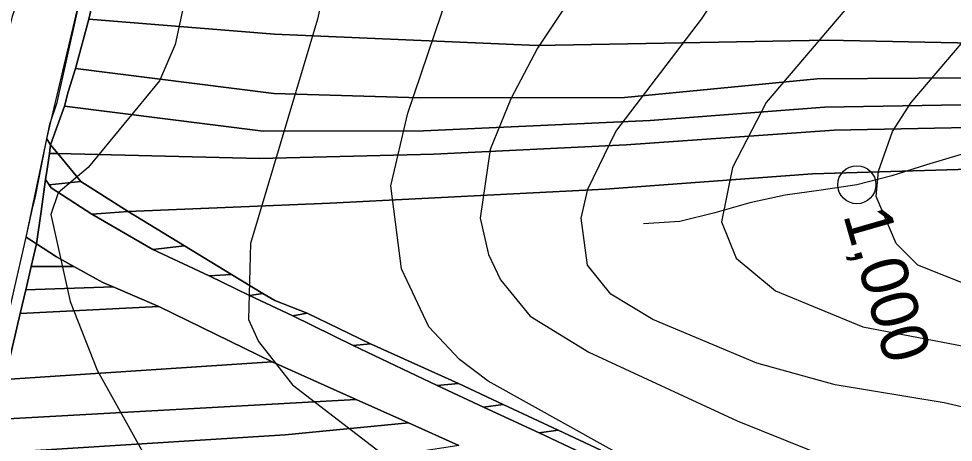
# Model space of a CAD drawing. Extents: x -510989 to -501240, y -1184665 to -1176098.
# Drawn here: x -510512.6 to -510254.5, y -1180348.9 to -1180231.9 of the extents above; entities that cross this region are included whole.
import ezdxf

# ---------------------------------------------------------------- set-up
doc = ezdxf.new("R2010")
doc.units = 0
for name, color, linetype in [('lesni_pozemek', 7, 'Continuous'), ('NAVRH_rozvodnice', 7, 'Continuous'), ('ostatni_plocha_x_ostatni_komunikace', 7, 'Continuous'), ('ostatni_plocha_x_silnice', 7, 'Continuous'), ('popis', 7, 'Continuous'), ('STAV_povodi', 7, 'Continuous'), ('trasovani_toku', 7, 'Continuous'), ('vrstevnice_01', 7, 'Continuous'), ('vrstevnice_02', 7, 'Continuous')]:
    doc.layers.add(name, color=color, linetype=linetype)

msp = doc.modelspace()

# ---------------------------------------------------------------- linework, layer by layer
at = {"layer": 'lesni_pozemek'}
for points in [[(-509976.21, -1180207.83), (-510053.14, -1180227.79), (-510097.37, -1180234.14), (-510131.29, -1180239.56), (-510208.41, -1180239.45), (-510289.34, -1180237.75), (-510369.43, -1180239.24), (-510441.97, -1180236.15), (-510493.25, -1180231.97), (-510490.8, -1180221.41), (-510439.3, -1180225.49), (-510373.63, -1180226.09), (-510299.64, -1180228.54), (-510217.22, -1180229.31), (-510131.92, -1180230.11), (-510096.09, -1180227.74), (-510054.98, -1180217.41), (-509976.43, -1180197.65)], [(-509978.83, -1180219.44), (-510095.15, -1180243.03), (-510141.46, -1180247.99), (-510208.48, -1180247.92), (-510292.16, -1180248.46), (-510345.34, -1180253.6), (-510401.71, -1180253.7), (-510442.19, -1180252.49), (-510496.95, -1180245.59), (-510493.25, -1180231.97), (-510441.97, -1180236.15), (-510369.43, -1180239.24), (-510289.34, -1180237.75), (-510208.41, -1180239.45), (-510131.29, -1180239.56), (-510097.37, -1180234.14), (-510053.14, -1180227.79), (-509976.21, -1180207.83)], [(-509982.33, -1180228.02), (-510010.82, -1180233.61), (-510050.96, -1180240.32), (-510082.98, -1180248.06), (-510141.78, -1180256.57), (-510209.33, -1180254.93), (-510290.12, -1180256.29), (-510338.24, -1180260), (-510400.79, -1180262.88), (-510445.12, -1180262.95), (-510499.99, -1180256), (-510498.92, -1180252.05), (-510496.95, -1180245.59), (-510442.19, -1180252.49), (-510401.71, -1180253.7), (-510345.34, -1180253.6), (-510292.16, -1180248.46), (-510208.48, -1180247.92), (-510141.46, -1180247.99), (-510095.15, -1180243.03), (-509978.83, -1180219.44)], [(-510011.1, -1180238), (-510020.32, -1180240.09), (-510080.31, -1180253.72), (-510141.54, -1180261.25), (-510222.72, -1180261.39), (-510287.42, -1180262.67), (-510344.9, -1180266.74), (-510397.95, -1180269.27), (-510446.13, -1180270.48), (-510501.79, -1180269.13), (-510503.79, -1180266.72), (-510499.99, -1180256), (-510445.12, -1180262.95), (-510400.79, -1180262.88), (-510338.24, -1180260), (-510290.12, -1180256.29), (-510209.33, -1180254.93), (-510141.78, -1180256.57), (-510082.98, -1180248.06), (-510050.96, -1180240.32), (-510010.82, -1180233.61)], [(-510019.77, -1180245.47), (-510025.75, -1180247), (-510024.37, -1180252.44), (-510049.58, -1180258.88), (-510074.58, -1180265.09), (-510127.81, -1180273.09), (-510135.55, -1180274.18), (-510175.03, -1180275.08), (-510222.23, -1180272.63), (-510293.37, -1180274.7), (-510350.62, -1180278.94), (-510426.62, -1180282.83), (-510482.39, -1180285.11), (-510495.43, -1180276.82), (-510501.79, -1180269.13), (-510446.13, -1180270.48), (-510397.95, -1180269.27), (-510344.9, -1180266.74), (-510287.42, -1180262.67), (-510222.72, -1180261.39), (-510141.54, -1180261.25), (-510080.31, -1180253.72), (-510020.32, -1180240.09)], [(-510502.15, -1180297.64), (-510497.34, -1180300.32), (-510509.16, -1180300.32), (-510507.71, -1180294.08)], [(-510509.16, -1180300.32), (-510497.34, -1180300.32), (-510489.41, -1180304.74), (-510486.54, -1180305.97), (-510510.66, -1180306.76)], [(-510510.66, -1180306.76), (-510486.54, -1180305.97), (-510473.89, -1180311.35), (-510512.19, -1180313.34)], [(-510473.89, -1180311.35), (-510442.62, -1180326.63), (-510516.44, -1180331.58), (-510512.19, -1180313.34)], [(-510516.44, -1180331.58), (-510442.62, -1180326.63), (-510419.42, -1180337.05), (-510518.99, -1180342.55)], [(-510518.99, -1180342.55), (-510419.42, -1180337.05), (-510404.98, -1180343.53), (-510439.03, -1180346.85), (-510521.19, -1180352)], [(-510404.98, -1180343.53), (-510391.06, -1180349.79), (-510423.89, -1180354.83), (-510523.59, -1180362.32), (-510521.19, -1180352), (-510439.03, -1180346.85)]]:
    msp.add_lwpolyline(points, close=True, dxfattribs=at)
msp.add_lwpolyline([(-510351.83, -1180351.05), (-510363.64, -1180345.53), (-510378.86, -1180338.45), (-510391.17, -1180332.69), (-510415.44, -1180321.67), (-510432.97, -1180313.17), (-510441.91, -1180309.76), (-510445.21, -1180307.75), (-510453.82, -1180302.51), (-510466.83, -1180294.58), (-510482.39, -1180285.11), (-510426.62, -1180282.83), (-510350.62, -1180278.94), (-510293.37, -1180274.7), (-510222.23, -1180272.63)], dxfattribs=at)
at = {"layer": 'NAVRH_rozvodnice'}
msp.add_arc((-510426.72, -1180257.64), 91.54, 153.6464, 172.807, dxfattribs=at)
at = {"layer": 'ostatni_plocha_x_ostatni_komunikace'}
for points in [[(-510513.58, -1180127.99), (-510512.03, -1180136.02), (-510510.77, -1180142.53), (-510509.13, -1180151.06), (-510507.55, -1180159.24), (-510505.88, -1180167.93), (-510502.92, -1180183.27), (-510494.49, -1180207.28), (-510492.02, -1180214.31), (-510490.29, -1180219.24), (-510490.8, -1180221.41), (-510493.25, -1180231.97), (-510496.95, -1180245.59), (-510498.92, -1180252.05), (-510499.99, -1180256), (-510503.79, -1180266.72), (-510504.8, -1180265.01), (-510504, -1180261), (-510502, -1180255), (-510494, -1180219), (-510506, -1180185), (-510544, -1179990)], [(-510530, -1180377), (-510510.58, -1180292.25), (-510507.71, -1180294.08), (-510509.16, -1180300.32), (-510510.66, -1180306.76), (-510512.19, -1180313.34), (-510516.44, -1180331.58), (-510518.99, -1180342.55), (-510521.19, -1180352)]]:
    msp.add_lwpolyline(points, dxfattribs=at)
at = {"layer": 'ostatni_plocha_x_silnice'}
for points in [[(-510503.79, -1180266.72), (-510504.13, -1180269.08), (-510504.76, -1180273.45), (-510505.17, -1180276.32), (-510506.43, -1180285.11), (-510507.71, -1180294.08), (-510510.58, -1180292.25), (-510508.57, -1180283.47), (-510508, -1180281), (-510506.21, -1180272.04), (-510504.8, -1180265.01)], [(-510503.79, -1180266.72), (-510501.79, -1180269.13), (-510504.13, -1180269.08)], [(-510501.79, -1180269.13), (-510495.43, -1180276.82), (-510500.7, -1180277.39), (-510504.18, -1180277.76), (-510505.17, -1180276.32), (-510504.76, -1180273.45), (-510504.13, -1180269.08)], [(-510495.43, -1180276.82), (-510482.39, -1180285.11), (-510489.8, -1180285.67), (-510492.4, -1180285.87), (-510503.63, -1180278.57), (-510504.18, -1180277.76), (-510500.7, -1180277.39)], [(-510489.8, -1180285.67), (-510482.39, -1180285.11), (-510466.83, -1180294.58), (-510475.6, -1180295.59), (-510492.4, -1180285.87)], [(-510475.6, -1180295.59), (-510466.83, -1180294.58), (-510453.82, -1180302.51), (-510460, -1180302.93)], [(-510460, -1180302.93), (-510453.82, -1180302.51), (-510445.21, -1180307.75), (-510448.85, -1180308.31)], [(-510448.85, -1180308.31), (-510445.21, -1180307.75), (-510441.91, -1180309.76), (-510432.97, -1180313.17), (-510436.91, -1180313.96)], [(-510436.91, -1180313.96), (-510432.97, -1180313.17), (-510415.44, -1180321.67), (-510420.29, -1180322.19)], [(-510420.29, -1180322.19), (-510415.44, -1180321.67), (-510391.17, -1180332.69), (-510397.07, -1180333.22)], [(-510391.17, -1180332.69), (-510378.86, -1180338.45), (-510384.24, -1180339.23), (-510397.07, -1180333.22)], [(-510378.86, -1180338.45), (-510363.64, -1180345.53), (-510368.89, -1180346.32), (-510384.24, -1180339.23)], [(-510368.89, -1180346.32), (-510363.64, -1180345.53), (-510351.83, -1180351.05), (-510357.21, -1180351.83)]]:
    msp.add_lwpolyline(points, close=True, dxfattribs=at)
msp.add_lwpolyline([(-510391.06, -1180349.79), (-510404.98, -1180343.53), (-510419.42, -1180337.05), (-510442.62, -1180326.63), (-510473.89, -1180311.35), (-510486.54, -1180305.97), (-510489.41, -1180304.74), (-510497.34, -1180300.32), (-510502.15, -1180297.64), (-510507.71, -1180294.08), (-510506.43, -1180285.11), (-510505.17, -1180276.32), (-510504.18, -1180277.76), (-510503.63, -1180278.57), (-510492.4, -1180285.87), (-510475.6, -1180295.59), (-510460, -1180302.93), (-510448.85, -1180308.31), (-510436.91, -1180313.96), (-510420.29, -1180322.19), (-510397.07, -1180333.22), (-510384.24, -1180339.23), (-510368.89, -1180346.32), (-510357.21, -1180351.83)], dxfattribs=at)
at = {"layer": 'popis'}
msp.add_lwpolyline([(-510622, -1180586), (-510612, -1180552), (-510587, -1180499), (-510562, -1180446), (-510530, -1180377), (-510520.29, -1180334.62), (-510510.58, -1180292.25), (-510504.8, -1180265.01), (-510494, -1180219), (-510506, -1180185), (-510525, -1180087.5), (-510544, -1179990)], dxfattribs=at)
at = {"layer": 'STAV_povodi'}
msp.add_arc((-510426.72, -1180257.64), 91.54, 153.6464, 172.807, dxfattribs=at)
at = {"layer": 'trasovani_toku'}
for p, q in [((-510252.35, -1180269.42), (-510261.93, -1180272.28)), ((-510261.93, -1180272.28), (-510271.49, -1180275.24)), ((-510271.49, -1180275.24), (-510281.17, -1180277.73)), ((-510281.17, -1180277.73), (-510291.05, -1180279.26)), ((-510300.96, -1180280.65), (-510310.74, -1180282.71)), ((-510291.05, -1180279.26), (-510300.96, -1180280.65)), ((-510310.74, -1180282.71), (-510320.34, -1180285.51)), ((-510320.34, -1180285.51), (-510330.06, -1180287.87)), ((-510330.06, -1180287.87), (-510340.04, -1180288.53))]:
    msp.add_line(p, q, dxfattribs=at)
msp.add_circle((-510281.17, -1180277.73), 5.25, dxfattribs=at)
at = {"layer": 'vrstevnice_01'}
for points in [[(-510226.91, -1180345), (-510257.09, -1180338), (-510287.19, -1180333), (-510308.81, -1180327), (-510337.5, -1180315), (-510349.09, -1180308), (-510355.5, -1180300), (-510357.31, -1180287), (-510355.41, -1180279), (-510347.69, -1180263), (-510324.09, -1180232), (-510305.59, -1180204), (-510290.5, -1180174), (-510281.91, -1180146), (-510278.81, -1180121), (-510280, -1180108), (-510283.91, -1180092), (-510296.81, -1180052), (-510300.19, -1180035), (-510301.41, -1180021), (-510297.19, -1179957)], [(-510429.81, -1179973), (-510434.41, -1180015), (-510434.41, -1180045), (-510430.31, -1180081), (-510431.41, -1180102), (-510460.41, -1180197), (-510469.41, -1180239), (-510473.69, -1180249), (-510493.41, -1180273)], [(-510339.81, -1180356), (-510383, -1180332), (-510390.91, -1180326), (-510399.31, -1180317), (-510406.91, -1180301), (-510409.81, -1180278), (-510405.19, -1180258), (-510394, -1180225), (-510375.31, -1180193), (-510360.81, -1180165), (-510352.91, -1180146), (-510349.41, -1180131), (-510348.41, -1180119), (-510351, -1180096), (-510367.19, -1180053), (-510368.31, -1180039), (-510367.91, -1180024), (-510360.41, -1179979)], [(-510012.5, -1180313), (-510054.5, -1180320), (-510112.5, -1180318), (-510149.31, -1180321), (-510182.41, -1180318), (-510240.81, -1180309), (-510249.09, -1180306), (-510264.31, -1180300), (-510270.31, -1180294), (-510275.81, -1180281), (-510275.19, -1180274), (-510271.31, -1180263), (-510266.19, -1180255), (-510223.69, -1180205), (-510206.69, -1180181), (-510197.41, -1180162), (-510191.19, -1180144), (-510188.91, -1180125), (-510191.69, -1180101), (-510196.81, -1180087), (-510225.69, -1180034), (-510235.09, -1180002)], [(-510493.41, -1180273), (-510501.69, -1180280), (-510503.69, -1180286), (-510498.41, -1180310), (-510490.91, -1180329), (-510467, -1180372), (-510464.19, -1180384), (-510465.41, -1180399), (-510467.81, -1180408), (-510475.69, -1180423), (-510496.41, -1180446), (-510520.31, -1180470), (-510530.91, -1180486), (-510538.31, -1180504), (-510543.91, -1180522), (-510547.31, -1180541), (-510549.5, -1180565), (-510550.19, -1180590)]]:
    msp.add_lwpolyline(points, dxfattribs=at)
at = {"layer": 'vrstevnice_02'}
for points in [[(-510326.41, -1179956), (-510339.5, -1180015), (-510339, -1180034), (-510336.69, -1180043), (-510318.5, -1180089), (-510314.81, -1180104), (-510313.19, -1180133), (-510322.09, -1180161), (-510339.31, -1180195), (-510369.31, -1180240), (-510376.69, -1180254), (-510382.41, -1180268), (-510385.19, -1180287), (-510382.91, -1180297), (-510379.59, -1180304), (-510371.41, -1180314), (-510355.19, -1180324), (-510314.19, -1180343), (-510266.91, -1180362), (-510251.09, -1180370)], [(-510264.91, -1180023), (-510235.19, -1180089), (-510228.81, -1180121), (-510228.81, -1180137), (-510231.5, -1180151), (-510240.59, -1180172), (-510269.69, -1180212), (-510306.19, -1180255), (-510315.5, -1180273), (-510318.5, -1180288), (-510314.5, -1180298), (-510303.59, -1180307), (-510279.5, -1180317), (-510154.09, -1180341), (-510109.69, -1180346), (-510082.09, -1180352), (-510067, -1180357), (-509991.69, -1180387)], [(-510401.41, -1180143), (-510421, -1180191), (-510430.09, -1180232), (-510448.59, -1180294), (-510449.19, -1180315), (-510446.41, -1180321), (-510437, -1180333), (-510375.91, -1180380), (-510370.31, -1180390), (-510367.81, -1180400), (-510368.5, -1180409), (-510373.19, -1180418), (-510424.41, -1180461), (-510438.81, -1180472), (-510478.31, -1180492), (-510500.31, -1180511), (-510506.81, -1180521), (-510512.81, -1180535), (-510516.19, -1180554), (-510514.31, -1180579), (-510517.91, -1180603)]]:
    msp.add_lwpolyline(points, dxfattribs=at)

# ---------------------------------------------------------------- texts
at = {"layer": 'trasovani_toku'}
msp.add_text('1,000', height=13, rotation=286.0844, dxfattribs=at).set_placement((-510285.01, -1180286.07))

doc.saveas('drawing.dxf')
